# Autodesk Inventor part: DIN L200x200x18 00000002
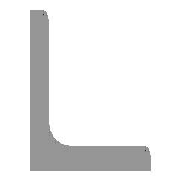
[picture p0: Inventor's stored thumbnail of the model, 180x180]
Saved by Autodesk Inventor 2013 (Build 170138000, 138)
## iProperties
IsCustomPart: 1
Created: 2009-11
Part Number: DIN L200x200x18 00000002
Material: Steel, Mild
Description: Hot-rolled structural steel section-Equal angles
Document SubType Name: Modeling
Standard: DIN
Designer: pokornp
Standard Revision: 1998
Standards Organization: DIN
Language: en-US
Size Designation: L200x200x18
Categories: <MemberInstance><Categories><Category DisplayName="Structural Shapes" InternalName="089c4875-fa83-4c05-b084-43b9cc11f5ed" Mnemonic="GRDR"><CategoryParameter Dis
Stock Number: L200x200x18
Density: 7.86 g/cm^3
Mass: 106464 g
Surface Area: 15515.4 cm^2
Volume: 13545.1 cm^3
_CCFamilyMember: 400
_CCFamilyDisplayName: DIN EN 10056-1 (Hot-rolled structural steel section-Equal angles) - Hot-rolled structural steel section-Equal angles
_FrameMemberDoc: Frame Member File
_Version: 15.0.0
G_L: 1960.000 mm
G_W: 200.000 mm
G_H: 200.000 mm
Author: pokornp
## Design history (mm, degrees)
node "Start plane"
node "End plane"
sketch "Sketch"
  geometry: L1 (-37.533, -19.533)-(-37.533, 135.467); L2 (-55.533, 144.467)-(-46.533, 144.467); L3 (-55.533, -55.533)-(-55.533, 144.467); L4 (-55.533, -55.533)-(144.467, -55.533); L5 (144.467, -46.533)-(144.467, -55.533); L6 (-19.533, -37.533)-(135.467, -37.533); L7 (0, 186.703)-(0, -95.906) reference; L8 (-95.906, 0)-(186.703, 0) reference; A1 r 18 centre (-19.533, -19.533) between (-37.533, -19.533) and (-19.533, -37.533); A2 r 9 centre (-46.533, 135.467) between (-37.533, 135.467) and (-46.533, 144.467); A3 r 9 centre (135.467, -46.533) between (144.467, -46.533) and (135.467, -37.533); 3 further points
  constraints: 12 end point, 6 point on circle, 6 point on line, 6 tangent, 3 centre point, 3 horizontal, 3 vertical, 1 equal radius
  dimensions: "d4" = 200 distance of L3.start L4.end (= b); "d6" = 200 distance of L3.start L2.start (= b); "d8" = 18 distance of point (144.467, -37.533) L4.end (= ParT); "d10" = 18 distance of L2.start point (-37.533, 144.467) (= ParT); "d17" = 18 radius of A1 (= R); "d18" = 9 radius of A2 (= R1); "d19" = 55.53331 distance between parallel lines of L8 L4 (= ex); "d20" = 55.53331 distance between parallel lines of L3 L7 (= d19)
extrude "Body" new body sketch "Sketch" stored distance "d11" = 1960 (= G_L); taper "d12" = 0 deg
node "Driven Length"
  sketch "Sketch3"
    geometry: L1 (0, 0)-(10, 0) reference
    constraints: 2 end point, 1 horizontal
  workplane "Work Plane10"
  sketch "Sketch4"
    geometry: L1 (-2, 0)-(12, 0) reference; L2 (-2, 1960)-(12, 1960) reference
    dimensions: "d24" = 1960 distance between parallel lines of L1 L2 (derived)
body "Solid1"
other parameters: "b" = 200 [user parameter; used in 3 equation terms], "ParT" = 18 [user parameter; used in 3 equation terms], "R" = 18 [user parameter; used in 1 equation term], "R1" = 9 [user parameter; used in 1 equation term], "G_L" = 1960 (= d24) [user parameter; used in 1 equation term], "d7" = 4 (derived), "d9" = 4 (derived), "ex" = 55.53331 (computed from b, ParT) [user parameter; used in 1 equation term], "G_OFFSET_START" = 0 [user parameter; used in 1 equation term], "G_OFFSET_END" = 0 [user parameter; used in 1 equation term], "d21" = 0 (computed from G_OFFSET_START), "d23" = 90 deg
